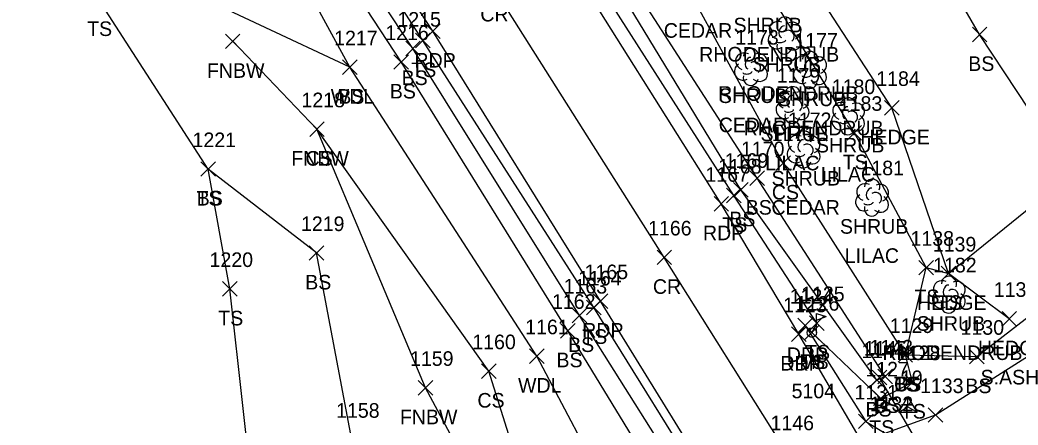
# Model space of a CAD drawing. Extents: x 1501299 to 1502485, y 381423 to 383765.
# Drawn here: x 1501751.5 to 1501888.1, y 382944 to 382999.5 of the extents above; entities that cross this region are included whole.
import ezdxf

# ---------------------------------------------------------------- set-up
doc = ezdxf.new("R2010")
doc.units = 0
for name, color, linetype in [('C_I', 7, 'Continuous'), ('CPSM', 7, 'Continuous'), ('D_A', 7, 'Continuous'), ('D_I', 7, 'Continuous'), ('D_TIC', 7, 'Continuous'), ('DCP', 7, 'Continuous'), ('L_A', 7, 'Continuous'), ('L_C', 7, 'Continuous'), ('L_I', 7, 'Continuous'), ('L_TIC', 7, 'Continuous'), ('LAHR', 7, 'Continuous'), ('LAWA', 7, 'Continuous'), ('LELB', 7, 'Continuous'), ('LFNC', 7, 'Continuous'), ('LMB', 7, 'Continuous'), ('LSH', 7, 'Continuous'), ('P_A', 7, 'Continuous'), ('P_I', 7, 'Continuous'), ('P_TIC', 7, 'Continuous'), ('PET', 7, 'Continuous'), ('PRC', 7, 'Continuous'), ('R_A', 7, 'Continuous'), ('R_I', 7, 'Continuous'), ('R_TIC', 7, 'Continuous'), ('RDP', 7, 'Continuous')]:
    doc.layers.add(name, color=color, linetype=linetype)

msp = doc.modelspace()

# ---------------------------------------------------------------- linework, layer by layer
at = {"layer": 'CPSM'}
for p, q in [((1501871.77, 382945.79), (1501873.02, 382947.96)), ((1501874.27, 382945.79), (1501873.02, 382947.96)), ((1501873.02, 382946.51), (1501873.02, 382947.96)), ((1501871.77, 382945.79), (1501873.02, 382946.51)), ((1501873.02, 382946.51), (1501873.02, 382946.51)), ((1501873.02, 382946.51), (1501874.27, 382945.79)), ((1501871.77, 382945.79), (1501874.27, 382945.79))]:
    msp.add_line(p, q, dxfattribs=at)
at = {"layer": 'D_TIC'}
for points in [[(1501868.12, 382949.54), (1501870.12, 382951.54)], [(1501870.12, 382949.54), (1501868.12, 382951.54)]]:
    msp.add_lwpolyline(points, dxfattribs=at)
at = {"layer": 'DCP'}
msp.add_lwpolyline([(1501884.4, 382924.48), (1501869.12, 382950.54)], dxfattribs=at)
at = {"layer": 'L_TIC'}
for points in [[(1501881.83, 382996.53), (1501883.83, 382998.53)], [(1501883.83, 382996.53), (1501881.83, 382998.53)], [(1501779.59, 382995.59), (1501781.59, 382997.59)], [(1501781.59, 382995.59), (1501779.59, 382997.59)], [(1501805.63, 382995.69), (1501807.63, 382997.69)], [(1501807.63, 382995.69), (1501805.63, 382997.69)], [(1501804.27, 382994.6), (1501806.27, 382996.6)], [(1501806.27, 382994.6), (1501804.27, 382996.6)], [(1501795.61, 382992.04), (1501797.61, 382994.04)], [(1501797.61, 382992.04), (1501795.61, 382994.04)], [(1501795.61, 382992.04), (1501797.61, 382994.04)], [(1501797.61, 382992.04), (1501795.61, 382994.04)], [(1501802.66, 382992.76), (1501804.66, 382994.76)], [(1501804.66, 382992.76), (1501802.66, 382994.76)], [(1501869.8, 382986.48), (1501871.8, 382988.48)], [(1501871.8, 382986.48), (1501869.8, 382988.48)], [(1501791.13, 382983.56), (1501793.13, 382985.56)], [(1501793.13, 382983.56), (1501791.13, 382985.56)], [(1501791.13, 382983.56), (1501793.13, 382985.56)], [(1501793.13, 382983.56), (1501791.13, 382985.56)], [(1501864.68, 382983.07), (1501866.68, 382985.07)], [(1501866.68, 382983.07), (1501864.68, 382985.07)], [(1501854.95, 382978.92), (1501856.95, 382980.92)], [(1501856.95, 382978.92), (1501854.95, 382980.92)], [(1501776.23, 382978.1), (1501778.23, 382980.1)], [(1501778.23, 382978.1), (1501776.23, 382980.1)], [(1501776.23, 382978.1), (1501778.23, 382980.1)], [(1501778.23, 382978.1), (1501776.23, 382980.1)], [(1501851.37, 382976.85), (1501853.37, 382978.85)], [(1501853.37, 382976.85), (1501851.37, 382978.85)], [(1501848.2, 382974.47), (1501850.2, 382976.47)], [(1501850.2, 382974.47), (1501848.2, 382976.47)], [(1501849.13, 382975.26), (1501851.13, 382977.26)], [(1501851.13, 382975.26), (1501849.13, 382977.26)], [(1501791.07, 382966.6), (1501793.07, 382968.6)], [(1501793.07, 382966.6), (1501791.07, 382968.6)], [(1501874.5, 382964.59), (1501876.5, 382966.59)], [(1501876.5, 382964.59), (1501874.5, 382966.59)], [(1501874.5, 382964.59), (1501876.5, 382966.59)], [(1501876.5, 382964.59), (1501874.5, 382966.59)], [(1501877.56, 382963.8), (1501879.56, 382965.8)], [(1501879.56, 382963.8), (1501877.56, 382965.8)], [(1501877.56, 382963.8), (1501879.56, 382965.8)], [(1501879.56, 382963.8), (1501877.56, 382965.8)], [(1501779.21, 382961.68), (1501781.21, 382963.68)], [(1501781.21, 382961.68), (1501779.21, 382963.68)], [(1501827.06, 382958.04), (1501829.06, 382960.04)], [(1501829.06, 382958.04), (1501827.06, 382960.04)], [(1501829.03, 382959.15), (1501831.03, 382961.15)], [(1501831.03, 382959.15), (1501829.03, 382961.15)], [(1501859.53, 382957), (1501861.53, 382959)], [(1501861.53, 382957), (1501859.53, 382959)], [(1501859.53, 382957), (1501861.53, 382959)], [(1501861.53, 382957), (1501859.53, 382959)], [(1501885.89, 382957.59), (1501887.89, 382959.59)], [(1501887.89, 382957.59), (1501885.89, 382959.59)], [(1501825.47, 382955.95), (1501827.47, 382957.95)], [(1501827.47, 382955.95), (1501825.47, 382957.95)], [(1501858.86, 382955.7), (1501860.86, 382957.7)], [(1501860.86, 382955.7), (1501858.86, 382957.7)], [(1501821.23, 382952.47), (1501823.23, 382954.47)], [(1501823.23, 382952.47), (1501821.23, 382954.47)], [(1501871.66, 382952.64), (1501873.66, 382954.64)], [(1501873.66, 382952.64), (1501871.66, 382954.64)], [(1501871.66, 382952.64), (1501873.66, 382954.64)], [(1501873.66, 382952.64), (1501871.66, 382954.64)], [(1501871.66, 382952.64), (1501873.66, 382954.64)], [(1501873.66, 382952.64), (1501871.66, 382954.64)], [(1501881.44, 382952.4), (1501883.44, 382954.4)], [(1501883.44, 382952.4), (1501881.44, 382954.4)], [(1501814.65, 382950.42), (1501816.65, 382952.42)], [(1501816.65, 382950.42), (1501814.65, 382952.42)], [(1501867.77, 382949.2), (1501869.77, 382951.2)], [(1501869.77, 382949.2), (1501867.77, 382951.2)], [(1501868.88, 382949.69), (1501870.88, 382951.69)], [(1501870.88, 382949.69), (1501868.88, 382951.69)], [(1501868.88, 382949.69), (1501870.88, 382951.69)], [(1501870.88, 382949.69), (1501868.88, 382951.69)], [(1501872.64, 382948.92), (1501874.64, 382950.92)], [(1501874.64, 382948.92), (1501872.64, 382950.92)], [(1501806, 382948.14), (1501808, 382950.14)], [(1501808, 382948.14), (1501806, 382950.14)], [(1501868.31, 382946.69), (1501870.31, 382948.69)], [(1501870.31, 382946.69), (1501868.31, 382948.69)]]:
    msp.add_lwpolyline(points, dxfattribs=at)
at = {"layer": 'LAHR'}
msp.add_lwpolyline([(1501886.89, 382958.59), (1501878.56, 382964.8), (1501870.8, 382987.48), (1501847.05, 383024.11), (1501835.93, 383042.93)], dxfattribs=at)
at = {"layer": 'LAWA'}
msp.add_lwpolyline([(1501942.68, 382714.84), (1501935.18, 382744.72), (1501913.34, 382785.2), (1501893.39, 382826.43), (1501865.29, 382869.92), (1501854.75, 382888.13), (1501835.93, 382927.55), (1501822.23, 382953.47), (1501796.61, 382993.04), (1501779.61, 383024.31), (1501754.16, 383064.05), (1501733.53, 383095.14)], dxfattribs=at)
at = {"layer": 'LELB'}
for points in [[(1501947.07, 382716.2), (1501936.79, 382745.62), (1501921.74, 382787.5), (1501900.17, 382829.78), (1501877.02, 382875.8), (1501866.17, 382892.91), (1501844.62, 382932.73), (1501828.06, 382959.04), (1501805.27, 382995.6), (1501783.69, 383028.16), (1501760.13, 383067.52), (1501734.81, 383103.88), (1501716.07, 383128.73), (1501702.98, 383136.28), (1501694.19, 383132.72)], [(1501947.96, 382716.12), (1501940, 382745.7), (1501923.41, 382788.32), (1501902.81, 382830.43), (1501868.96, 382893.88), (1501846.4, 382933.73), (1501830.03, 382960.15), (1501806.63, 382996.69), (1501785.68, 383029.2), (1501761.09, 383068.04), (1501736.24, 383105.32), (1501718.86, 383131.58)], [(1501945.34, 382716.14), (1501936.67, 382745.19), (1501918.39, 382786.66), (1501897.88, 382827.99), (1501871.61, 382874.07), (1501860.42, 382890.26), (1501841.87, 382931.65), (1501826.47, 382956.95), (1501803.66, 382993.76), (1501782.06, 383026.73), (1501758.57, 383066.64), (1501733.62, 383102.86), (1501712.41, 383124.49), (1501694.92, 383122.17), (1501687.27, 383121.66)], [(1501869.88, 382950.69), (1501868.77, 382950.2), (1501850.13, 382976.26), (1501827.93, 383012.86), (1501805.25, 383045.65), (1501793.26, 383066.92), (1501794.32, 383067.43), (1501799.89, 383080.74), (1501815.83, 383095.83), (1501838.89, 383122.31)], [(1501783.59, 382899.61), (1501783.94, 382929.09), (1501780.21, 382962.68), (1501777.23, 382979.1), (1501762.26, 383002.32), (1501757.64, 383021.11), (1501754.69, 383033.79), (1501751.14, 383043.33), (1501742.41, 383064.13), (1501735.88, 383077.84), (1501726.8, 383086.93), (1501711.19, 383095.35), (1501693.41, 383100.22), (1501689.59, 383108.9)], [(1501872.66, 382953.64), (1501855.95, 382979.92), (1501835.17, 383018.01), (1501808.76, 383051.57), (1501808.19, 383064.92), (1501807.02, 383075.45), (1501821.18, 383087.2), (1501841.55, 383105.55)], [(1501860.53, 382958), (1501859.86, 382956.7), (1501869.31, 382947.69), (1501873.64, 382949.92), (1501872.66, 382953.64), (1501875.5, 382965.59), (1501865.68, 382984.07), (1501840.59, 383025.51), (1501826.61, 383049.7), (1501821.73, 383060.17), (1501823.1, 383069.92), (1501837.38, 383078.16), (1501846.45, 383083.09)], [(1501875.5, 382965.59), (1501878.56, 382964.8), (1501896.79, 382979.52), (1501894.94, 382998.89), (1501871.36, 383036.08), (1501850.54, 383070.75), (1501846.45, 383083.09)], [(1501860.53, 382958), (1501849.2, 382975.47), (1501826.17, 383011.49), (1501803.93, 383045.2), (1501790.59, 383066.15), (1501793.35, 383069.12), (1501796.83, 383082.64)], [(1501869.88, 382950.69), (1501852.37, 382977.85), (1501829.36, 383013.65), (1501805.88, 383046.72), (1501796.14, 383066.96), (1501799.89, 383080.74)], [(1501896.79, 382979.52), (1501889.64, 382987.15), (1501882.83, 382997.53), (1501862.66, 383032.28), (1501842.54, 383064.76), (1501837.38, 383078.16)], [(1501796.61, 382993.04), (1501772.08, 383004.59), (1501765.26, 383019.56)], [(1501865.29, 382869.92), (1501843.57, 382887.06), (1501825.25, 382920.85), (1501815.65, 382951.42), (1501792.13, 382984.56)], [(1501808.67, 382909.79), (1501796.88, 382942.03), (1501792.07, 382967.6), (1501777.23, 382979.1)], [(1501872.66, 382953.64), (1501882.44, 382953.4), (1501904.5, 382970.43)]]:
    msp.add_lwpolyline(points, dxfattribs=at)
at = {"layer": 'LFNC'}
msp.add_lwpolyline([(1501823.33, 382918.61), (1501807, 382949.14), (1501792.13, 382984.56), (1501780.59, 382996.59)], dxfattribs=at)
at = {"layer": 'LMB'}
for p, q in [((1501860.51, 382959.3), (1501861.81, 382958.92)), ((1501860.52, 382956.71), (1501860.52, 382959.3)), ((1501860.52, 382958.4), (1501861.8, 382958.91)), ((1501859.86, 382956.7), (1501859.86, 382956.7))]:
    msp.add_line(p, q, dxfattribs=at)
msp.add_circle((1501859.86, 382956.7), 0.656, dxfattribs=at)
at = {"layer": 'LSH'}
for p, q in [((1501856.12, 382997.44), (1501856.12, 382997.44)), ((1501856.12, 382997.44), (1501856.12, 382997.44)), ((1501851.51, 382993.14), (1501851.51, 382993.14)), ((1501851.51, 382993.14), (1501851.51, 382993.14)), ((1501859.59, 382992.71), (1501859.59, 382992.71)), ((1501859.59, 382992.71), (1501859.59, 382992.71)), ((1501857.2, 382987.92), (1501857.2, 382987.92)), ((1501857.2, 382987.92), (1501857.2, 382987.92)), ((1501864.8, 382986.37), (1501864.8, 382986.37)), ((1501864.8, 382986.37), (1501864.8, 382986.37)), ((1501858.72, 382981.84), (1501858.72, 382981.84)), ((1501858.72, 382981.84), (1501858.72, 382981.84)), ((1501868.08, 382975.24), (1501868.08, 382975.24)), ((1501868.08, 382975.24), (1501868.08, 382975.24)), ((1501878.59, 382961.94), (1501878.59, 382961.94)), ((1501878.59, 382961.94), (1501878.59, 382961.94))]:
    msp.add_line(p, q, dxfattribs=at)
for centre in [(1501856.16, 382998.88), (1501851.55, 382994.58), (1501859.64, 382994.15), (1501857.24, 382989.35), (1501864.85, 382987.8), (1501858.77, 382983.28), (1501868.13, 382976.67), (1501878.64, 382963.38)]:
    msp.add_arc(centre, 1.05, 335.5272, 180.9563, dxfattribs=at)
for centre, major_axis, ratio, start_param, end_param in [((1501855.32, 382998.11), (1.21, -0.51), 0.895232, 1.570796, 4.712389), ((1501855.91, 382997.9), (-0.208, -0.792), 0.645439, 3.141593, 6.283185), ((1501856.62, 382997.28), (-0.5, 0.667), 0.989748, 3.141593, 6.283185), ((1501857.16, 382998.03), (-1.14, -0.48), 0.949671, 1.570796, 4.712389), ((1501855.03, 382996.74), (0.58, -1.04), 0.959034, 3.141593, 6.283185), ((1501855.66, 382996.69), (-0.625, -0.083), 0.423636, 0, 3.141593), ((1501857.12, 382996.61), (-1.09, 0.79), 0.841452, 1.570796, 4.712389), ((1501856.12, 382995.94), (0.26, 1.06), 0.942809, 1.570796, 4.712389), ((1501850.72, 382993.81), (1.21, -0.51), 0.895232, 1.570796, 4.712389), ((1501851.3, 382993.6), (-0.208, -0.792), 0.645439, 3.141593, 6.283185), ((1501852.55, 382993.73), (-1.14, -0.48), 0.949671, 1.570796, 4.712389), ((1501858.8, 382993.38), (1.21, -0.51), 0.895232, 1.570796, 4.712389), ((1501860.64, 382993.3), (-1.14, -0.48), 0.949671, 1.570796, 4.712389), ((1501850.42, 382992.43), (0.58, -1.04), 0.959034, 3.141593, 6.283185), ((1501852.01, 382992.98), (-0.5, 0.667), 0.989748, 3.141593, 6.283185), ((1501852.51, 382992.31), (-1.09, 0.79), 0.841452, 1.570796, 4.712389), ((1501858.51, 382992.01), (0.58, -1.04), 0.959034, 3.141593, 6.283185), ((1501859.39, 382993.17), (-0.208, -0.792), 0.645439, 3.141593, 6.283185), ((1501860.09, 382992.55), (-0.5, 0.667), 0.989748, 3.141593, 6.283185), ((1501860.59, 382991.88), (-1.09, 0.79), 0.841452, 1.570796, 4.712389), ((1501851.51, 382991.64), (0.26, 1.06), 0.942809, 1.570796, 4.712389), ((1501851.05, 382992.39), (-0.625, -0.083), 0.423636, 0, 3.141593), ((1501859.59, 382991.21), (0.26, 1.06), 0.942809, 1.570796, 4.712389), ((1501859.14, 382991.96), (-0.625, -0.083), 0.423636, 0, 3.141593), ((1501856.41, 382988.58), (1.21, -0.51), 0.895232, 1.570796, 4.712389), ((1501856.99, 382988.37), (-0.208, -0.792), 0.645439, 3.141593, 6.283185), ((1501857.7, 382987.75), (-0.5, 0.667), 0.989748, 3.141593, 6.283185), ((1501858.24, 382988.5), (-1.14, -0.48), 0.949671, 1.570796, 4.712389), ((1501856.11, 382987.21), (0.58, -1.04), 0.959034, 3.141593, 6.283185), ((1501856.74, 382987.17), (-0.625, -0.083), 0.423636, 0, 3.141593), ((1501858.2, 382987.08), (-1.09, 0.79), 0.841452, 1.570796, 4.712389), ((1501864.01, 382987.03), (1.21, -0.51), 0.895232, 1.570796, 4.712389), ((1501864.59, 382986.82), (-0.208, -0.792), 0.645439, 3.141593, 6.283185), ((1501865.84, 382986.95), (-1.14, -0.48), 0.949671, 1.570796, 4.712389), ((1501857.2, 382986.42), (0.26, 1.06), 0.942809, 1.570796, 4.712389), ((1501863.72, 382985.66), (0.58, -1.04), 0.959034, 3.141593, 6.283185), ((1501865.3, 382986.2), (-0.5, 0.667), 0.989748, 3.141593, 6.283185), ((1501865.8, 382985.53), (-1.09, 0.79), 0.841452, 1.570796, 4.712389), ((1501864.8, 382984.87), (0.26, 1.06), 0.942809, 1.570796, 4.712389), ((1501864.34, 382985.62), (-0.625, -0.083), 0.423636, 0, 3.141593), ((1501857.93, 382982.51), (1.21, -0.51), 0.895232, 1.570796, 4.712389), ((1501858.51, 382982.3), (-0.208, -0.792), 0.645439, 3.141593, 6.283185), ((1501859.76, 382982.43), (-1.14, -0.48), 0.949671, 1.570796, 4.712389), ((1501857.64, 382981.13), (0.58, -1.04), 0.959034, 3.141593, 6.283185), ((1501859.22, 382981.68), (-0.5, 0.667), 0.989748, 3.141593, 6.283185), ((1501859.72, 382981.01), (-1.09, 0.79), 0.841452, 1.570796, 4.712389), ((1501858.72, 382980.34), (0.26, 1.06), 0.942809, 1.570796, 4.712389), ((1501858.26, 382981.09), (-0.625, -0.083), 0.423636, 0, 3.141593), ((1501867.29, 382975.9), (1.21, -0.51), 0.895232, 1.570796, 4.712389), ((1501867.87, 382975.7), (-0.208, -0.792), 0.645439, 3.141593, 6.283185), ((1501869.12, 382975.82), (-1.14, -0.48), 0.949671, 1.570796, 4.712389), ((1501867, 382974.53), (0.58, -1.04), 0.959034, 3.141593, 6.283185), ((1501868.58, 382975.07), (-0.5, 0.667), 0.989748, 3.141593, 6.283185), ((1501869.08, 382974.4), (-1.09, 0.79), 0.841452, 1.570796, 4.712389), ((1501868.08, 382973.74), (0.26, 1.06), 0.942809, 1.570796, 4.712389), ((1501867.62, 382974.49), (-0.625, -0.083), 0.423636, 0, 3.141593), ((1501877.8, 382962.61), (1.21, -0.51), 0.895232, 1.570796, 4.712389), ((1501878.39, 382962.4), (-0.208, -0.792), 0.645439, 3.141593, 6.283185), ((1501879.09, 382961.77), (-0.5, 0.667), 0.989748, 3.141593, 6.283185), ((1501879.64, 382962.52), (-1.14, -0.48), 0.949671, 1.570796, 4.712389), ((1501877.51, 382961.23), (0.58, -1.04), 0.959034, 3.141593, 6.283185), ((1501878.14, 382961.19), (-0.625, -0.083), 0.423636, 0, 3.141593), ((1501879.59, 382961.11), (-1.09, 0.79), 0.841452, 1.570796, 4.712389), ((1501878.59, 382960.44), (0.26, 1.06), 0.942809, 1.570796, 4.712389)]:
    msp.add_ellipse(centre, major_axis=major_axis, ratio=ratio, start_param=start_param, end_param=end_param, dxfattribs=at)
at = {"layer": 'P_TIC'}
for points in [[(1501806.98, 382996.99), (1501808.98, 382998.99)], [(1501808.98, 382996.99), (1501806.98, 382998.99)], [(1501846.47, 382973.35), (1501848.47, 382975.35)], [(1501848.47, 382973.35), (1501846.47, 382975.35)], [(1501838.67, 382966), (1501840.67, 382968)], [(1501840.67, 382966), (1501838.67, 382968)], [(1501829.94, 382960.01), (1501831.94, 382962.01)], [(1501831.94, 382960.01), (1501829.94, 382962.01)], [(1501857.07, 382955.49), (1501859.07, 382957.49)], [(1501859.07, 382955.49), (1501857.07, 382957.49)]]:
    msp.add_lwpolyline(points, dxfattribs=at)
at = {"layer": 'PET'}
for points in [[(1501949.65, 382716.51), (1501941.04, 382745.98), (1501925.01, 382788.59), (1501904.25, 382831.62), (1501880.76, 382877.89), (1501870.56, 382894.72), (1501847.41, 382934.27), (1501830.94, 382961.01), (1501807.98, 382997.99), (1501787.08, 383029.95), (1501762.26, 383068.78), (1501737.38, 383106.29), (1501722.89, 383129.67), (1501696.7, 383166.34)], [(1501971.37, 382720.65), (1501961.03, 382754.71), (1501942.93, 382798.84), (1501931, 382825.08), (1501924.58, 382839.6), (1501916.53, 382851.6), (1501908.31, 382868.39), (1501899.17, 382885.53), (1501887.9, 382904.2), (1501878.51, 382922.49), (1501869.74, 382936.53), (1501858.07, 382956.49), (1501847.47, 382974.35), (1501824.87, 383010.25), (1501802.29, 383043.8), (1501787.99, 383066.09), (1501768.48, 383096.75)]]:
    msp.add_lwpolyline(points, dxfattribs=at)
at = {"layer": 'PRC'}
msp.add_lwpolyline([(1501960.61, 382718.65), (1501950.96, 382750.48), (1501934.96, 382791.85), (1501913.07, 382836.93), (1501889.31, 382881.38), (1501879.24, 382899.51), (1501856.39, 382940.32), (1501839.67, 382967), (1501816.06, 383004.31), (1501794.78, 383036.25), (1501769.81, 383075.16), (1501745.79, 383111.56), (1501729.43, 383136), (1501711.24, 383163.53), (1501694.82, 383188.2), (1501683.55, 383204), (1501664.64, 383231.24), (1501639.52, 383268.34), (1501626.39, 383287.88)], dxfattribs=at)
at = {"layer": 'R_TIC'}
for points in [[(1501857.95, 382956.67), (1501859.95, 382958.67)], [(1501859.95, 382956.67), (1501857.95, 382958.67)], [(1501857.07, 382955.49), (1501859.07, 382957.49)], [(1501859.07, 382955.49), (1501857.07, 382957.49)], [(1501875.8, 382944.41), (1501877.8, 382946.41)], [(1501877.8, 382944.41), (1501875.8, 382946.41)], [(1501866.27, 382943.54), (1501868.27, 382945.54)], [(1501868.27, 382943.54), (1501866.27, 382945.54)]]:
    msp.add_lwpolyline(points, dxfattribs=at)
at = {"layer": 'RDP'}
msp.add_lwpolyline([(1501858.07, 382956.49), (1501858.95, 382957.67), (1501867.27, 382944.54), (1501869.91, 382942.93), (1501876.8, 382945.41), (1501892.37, 382955.34), (1501908.29, 382967.13)], dxfattribs=at)

# ---------------------------------------------------------------- texts
at = {"layer": 'C_I'}
msp.add_text('10', height=2, dxfattribs=at).set_placement((1501872.04, 382949.51))
at = {"layer": 'D_A'}
msp.add_text('P', height=2, dxfattribs=at).set_placement((1501868.5, 382945.54))
at = {"layer": 'D_I'}
msp.add_text('1145', height=2, dxfattribs=at).set_placement((1501866.99, 382953.54))
at = {"layer": 'L_A'}
for s, p in [('SHRUB', (1501849.15, 382997.82)), ('TS', (1501760.67, 382997.32)), ('SHRUB', (1501851.75, 382992.44)), ('BS', (1501881.27, 382992.53)), ('FNBW', (1501777.07, 382991.59)), ('TS', (1501805.04, 382991.69)), ('BS', (1501803.71, 382990.6)), ('WDL', (1501794.02, 382988.04)), ('BS', (1501795.05, 382988.04)), ('BS', (1501802.1, 382988.76)), ('SHRUB', (1501847.14, 382988.14)), ('SHRUB', (1501855.22, 382987.71)), ('SHRUB', (1501852.83, 382982.92)), ('HEDGE', (1501866.5, 382982.48)), ('SHRUB', (1501860.43, 382981.37)), ('FNBW', (1501788.61, 382979.56)), ('CS', (1501790.57, 382979.56)), ('TS', (1501864.09, 382979.07)), ('SHRUB', (1501854.35, 382976.84)), ('CS', (1501854.39, 382974.92)), ('TS', (1501775.64, 382974.1)), ('BS', (1501775.67, 382974.1)), ('BS', (1501850.81, 382972.85)), ('TS', (1501847.61, 382970.47)), ('BS', (1501848.57, 382971.26)), ('SHRUB', (1501863.71, 382970.24)), ('BS', (1501790.52, 382962.6)), ('TS', (1501873.91, 382960.59)), ('TS', (1501873.91, 382960.59)), ('HEDGE', (1501874.26, 382959.8)), ('TS', (1501876.97, 382959.8)), ('TS', (1501778.62, 382957.68)), ('SHRUB', (1501874.22, 382956.94)), ('TS', (1501828.44, 382955.15)), ('BS', (1501826.5, 382954.04)), ('TS', (1501858.94, 382953)), ('TS', (1501858.94, 382953)), ('HEDGE', (1501882.59, 382953.59)), ('BS', (1501824.91, 382951.95)), ('TS', (1501858.27, 382951.7)), ('MB', (1501858.17, 382951.7)), ('WDL', (1501819.65, 382948.47)), ('TS', (1501871.07, 382948.64)), ('CS', (1501871.11, 382948.64)), ('BS', (1501871.11, 382948.64)), ('BS', (1501880.88, 382948.4)), ('CS', (1501814.09, 382946.42)), ('BS', (1501868.32, 382945.69)), ('BS', (1501868.32, 382945.69)), ('BS', (1501867.21, 382945.2)), ('TS', (1501872.05, 382944.92)), ('FNBW', (1501803.48, 382944.14)), ('TS', (1501867.72, 382942.69))]:
    msp.add_text(s, height=2, dxfattribs=at).set_placement(p)
at = {"layer": 'L_C'}
for s, p in [('CEDAR', (1501839.6, 382997.08)), ('RHODENDRUB', (1501844.44, 382993.82)), ('RHODENDRUB', (1501847.04, 382988.44)), ('CEDAR', (1501847.12, 382984.14)), ('RHODENDRUB', (1501850.52, 382983.71)), ('LILAC', (1501853.47, 382978.92)), ('LILAC', (1501861.08, 382977.37)), ('CEDAR', (1501854.33, 382972.84)), ('LILAC', (1501864.36, 382966.24)), ('RHODENDRUB', (1501869.52, 382952.94)), ('S.ASH', (1501882.96, 382949.59)), ('5104', (1501857.09, 382947.7))]:
    msp.add_text(s, height=2, dxfattribs=at).set_placement(p)
at = {"layer": 'L_I'}
for s, p in [('1215', (1501803.14, 382998.6)), ('1216', (1501801.48, 382996.76)), ('1173', (1501849.38, 382996.14)), ('1217', (1501794.48, 382996.04)), ('1217', (1501794.48, 382996.04)), ('1177', (1501857.47, 382995.71)), ('1179', (1501855.06, 382990.92)), ('1180', (1501862.59, 382989.37)), ('1184', (1501868.68, 382990.48)), ('1218', (1501790.01, 382987.56)), ('1218', (1501790.01, 382987.56)), ('1183', (1501863.55, 382987.07)), ('1172', (1501856.59, 382984.84)), ('1171', (1501854.39, 382982.92)), ('1221', (1501775.1, 382982.1)), ('1221', (1501775.1, 382982.1)), ('1170', (1501850.16, 382980.85)), ('1168', (1501847.03, 382978.47)), ('1169', (1501847.94, 382979.26)), ('1181', (1501866.52, 382978.24)), ('1219', (1501789.94, 382970.6)), ('1138', (1501873.37, 382968.59)), ('1138', (1501873.37, 382968.59)), ('1139', (1501876.42, 382967.8)), ('1139', (1501876.42, 382967.8)), ('1220', (1501777.43, 382965.68)), ('1182', (1501876.47, 382964.94)), ('1163', (1501825.89, 382962.04)), ('1164', (1501827.86, 382963.15)), ('1125', (1501858.4, 382961)), ('1125', (1501858.4, 382961)), ('1137', (1501884.76, 382961.59)), ('1162', (1501824.3, 382959.95)), ('1126', (1501857.68, 382959.7)), ('1126', (1501857.68, 382959.7)), ('1129', (1501870.53, 382956.64)), ('1129', (1501870.53, 382956.64)), ('1129', (1501870.53, 382956.64)), ('1161', (1501820.63, 382956.47)), ('1130', (1501880.22, 382956.4)), ('1160', (1501813.39, 382954.42)), ('1144', (1501866.64, 382953.2)), ('1143', (1501867.76, 382953.69)), ('1143', (1501867.76, 382953.69)), ('1128', (1501871.52, 382952.92)), ('1159', (1501804.87, 382952.14)), ('1127', (1501867.19, 382950.69)), ('1158', (1501794.75, 382945.03))]:
    msp.add_text(s, height=2, dxfattribs=at).set_placement(p)
at = {"layer": 'P_A'}
for s, p in [('CR', (1501814.49, 382999.31)), ('RDP', (1501805.47, 382992.99)), ('RDP', (1501844.96, 382969.35)), ('CR', (1501838.11, 382962)), ('RDP', (1501828.43, 382956.01)), ('RDP', (1501855.55, 382951.49))]:
    msp.add_text(s, height=2, dxfattribs=at).set_placement(p)
at = {"layer": 'P_I'}
for s, p in [('1167', (1501845.3, 382977.35)), ('1166', (1501837.45, 382970)), ('1165', (1501828.76, 382964.01)), ('1123', (1501855.94, 382959.49)), ('1146', (1501854.21, 382943.32))]:
    msp.add_text(s, height=2, dxfattribs=at).set_placement(p)
at = {"layer": 'R_A'}
for p in [(1501856.44, 382952.67), (1501855.55, 382951.49)]:
    msp.add_text('DRP', height=2, dxfattribs=at).set_placement(p)
at = {"layer": 'R_I'}
for s, p in [('1124', (1501856.83, 382960.67)), ('1123', (1501855.94, 382959.49)), ('1133', (1501874.67, 382948.41)), ('1131', (1501865.71, 382947.54)), ('1132', (1501867.78, 382945.93))]:
    msp.add_text(s, height=2, dxfattribs=at).set_placement(p)

doc.saveas('drawing.dxf')
